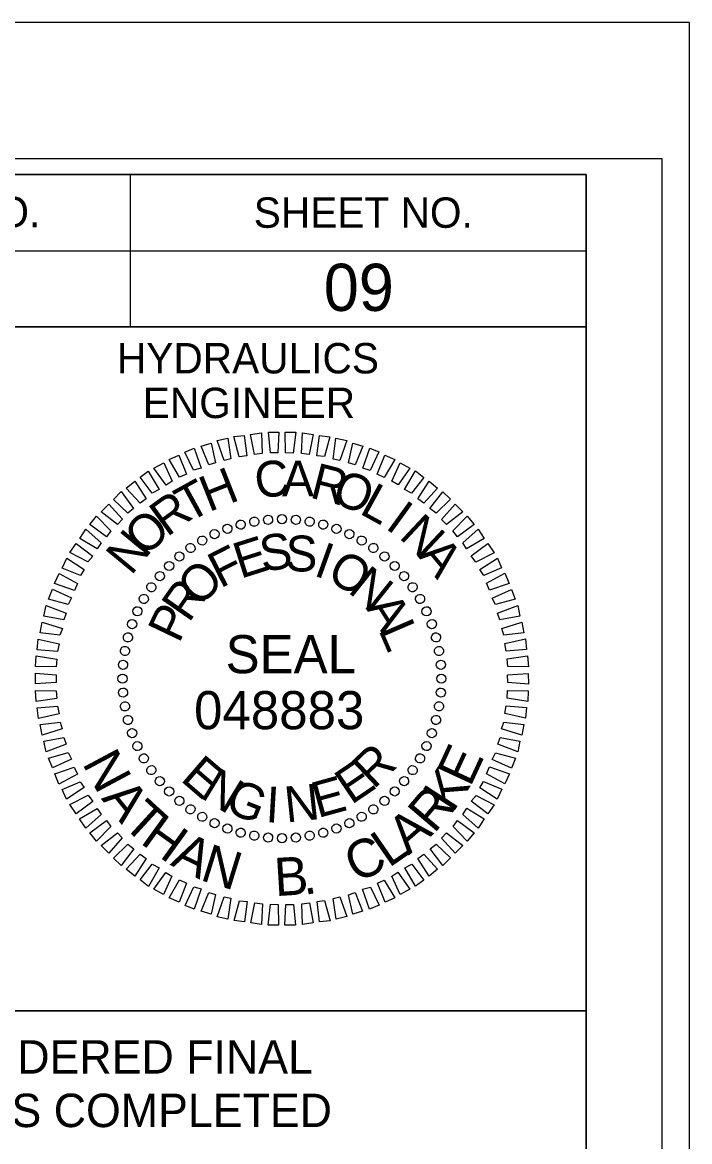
# Model space of a CAD drawing. Extents: x 1648862 to 1650739, y 844691 to 845791.
# Drawn here: x 1650436.5 to 1650546.3, y 845606.9 to 845791 of the extents above; entities that cross this region are included whole.
import ezdxf

# ---------------------------------------------------------------- set-up
doc = ezdxf.new("R2010")
doc.units = 0
for name, color, linetype in [('Default', 7, 'Continuous'), ('Prop Breaking of Exist Asph Pvmt', 7, 'Continuous'), ('Prop Conc Barrier Transition Section', 7, 'Continuous'), ('Prop Conc Drive Drop Type', 7, 'Continuous'), ('Prop DGN Element Guardrail', 7, 'Continuous'), ('Prop Easement Construction', 7, 'Continuous'), ('Prop Fence Woven Wire', 7, 'Continuous')]:
    doc.layers.add(name, color=color, linetype=linetype)

msp = doc.modelspace()

# ---------------------------------------------------------------- linework, layer by layer
at = {"layer": 'Prop Conc Barrier Transition Section'}
msp.add_lwpolyline([(1648862.28, 844691.02), (1650546.28, 844691.02), (1650546.28, 845791.02), (1648862.28, 845791.02)], close=True, dxfattribs=at)
at = {"layer": 'Prop Conc Drive Drop Type'}
for p, q in [((1650329.23, 845628.47), (1650529.27, 845628.47)), ((1650329.23, 845628.47), (1650529.27, 845628.47)), ((1650529.27, 845628.46), (1650529.27, 845604.96)), ((1650529.27, 845628.46), (1650529.27, 845604.96))]:
    msp.add_line(p, q, dxfattribs=at)
at = {"layer": 'Prop DGN Element Guardrail'}
for p, q in [((1650454.28, 845765.97), (1650454.28, 845740.97)), ((1650329.23, 845753.47), (1650529.28, 845753.47))]:
    msp.add_line(p, q, dxfattribs=at)
for points in [[(1650529.28, 845766.02), (1649029.28, 845766.02), (1649029.28, 844716.02), (1650529.28, 844716.02)], [(1650329.23, 845766.02), (1650529.28, 845766.02), (1650529.28, 845740.97), (1650329.23, 845740.97)], [(1650429.28, 845740.97), (1650529.28, 845740.97), (1650529.28, 845628.47), (1650429.28, 845628.47)]]:
    msp.add_lwpolyline(points, close=True, dxfattribs=at)
at = {"layer": 'Prop Easement Construction'}
msp.add_lwpolyline([(1648875.28, 844713.47), (1650541.78, 844713.47), (1650541.78, 845768.57), (1648875.28, 845768.57)], close=True, dxfattribs=at)
at = {"layer": 'Prop Fence Woven Wire'}
for p, q in [((1650472.41, 845708.44), (1650472.41, 845708.44)), ((1650474.7, 845708.89), (1650474.7, 845708.89)), ((1650476.94, 845709.25), (1650476.94, 845709.25)), ((1650479.24, 845709.34), (1650479.24, 845709.34)), ((1650481.55, 845709.22), (1650481.55, 845709.22)), ((1650483.8, 845708.9), (1650483.8, 845708.9)), ((1650486.01, 845708.46), (1650486.01, 845708.46)), ((1650468.15, 845706.9), (1650468.15, 845706.9)), ((1650470.22, 845707.77), (1650470.22, 845707.77)), ((1650488.21, 845707.77), (1650488.21, 845707.77)), ((1650490.32, 845706.87), (1650490.32, 845706.87)), ((1650464.16, 845704.58), (1650464.16, 845704.58)), ((1650466.13, 845705.82), (1650466.13, 845705.82)), ((1650492.38, 845705.86), (1650492.38, 845705.86)), ((1650494.28, 845704.58), (1650494.28, 845704.58)), ((1650462.35, 845703.24), (1650462.35, 845703.24)), ((1650496.14, 845703.2), (1650496.14, 845703.2)), ((1650460.66, 845701.64), (1650460.66, 845701.64)), ((1650497.79, 845701.66), (1650497.79, 845701.66)), ((1650459.12, 845699.99), (1650459.12, 845699.99)), ((1650499.38, 845699.96), (1650499.38, 845699.96)), ((1650457.74, 845698.14), (1650457.74, 845698.14)), ((1650500.72, 845698.16), (1650500.72, 845698.16)), ((1650456.46, 845696.23), (1650456.46, 845696.23)), ((1650501.96, 845696.19), (1650501.96, 845696.19)), ((1650455.45, 845694.18), (1650455.45, 845694.18)), ((1650503.04, 845694.17), (1650503.04, 845694.17)), ((1650454.55, 845692.07), (1650454.55, 845692.07)), ((1650503.91, 845692.09), (1650503.91, 845692.09)), ((1650453.85, 845689.86), (1650453.85, 845689.86)), ((1650504.58, 845689.91), (1650504.58, 845689.91)), ((1650453.42, 845687.66), (1650453.42, 845687.66)), ((1650505.04, 845687.62), (1650505.04, 845687.62)), ((1650453.1, 845685.4), (1650453.1, 845685.4)), ((1650505.39, 845685.37), (1650505.39, 845685.37)), ((1650452.98, 845683.1), (1650452.98, 845683.1)), ((1650479.23, 845683.09), (1650479.23, 845683.09)), ((1650505.48, 845683.07), (1650505.48, 845683.07)), ((1650453.07, 845680.8), (1650453.07, 845680.8)), ((1650505.37, 845680.77), (1650505.37, 845680.77)), ((1650453.42, 845678.56), (1650453.42, 845678.56)), ((1650505.04, 845678.52), (1650505.04, 845678.52)), ((1650453.88, 845676.26), (1650453.88, 845676.26)), ((1650504.61, 845676.31), (1650504.61, 845676.31)), ((1650454.55, 845674.08), (1650454.55, 845674.08)), ((1650503.92, 845674.1), (1650503.92, 845674.1)), ((1650455.42, 845672), (1650455.42, 845672)), ((1650503.01, 845672), (1650503.01, 845672)), ((1650456.5, 845669.98), (1650456.5, 845669.98)), ((1650502, 845669.94), (1650502, 845669.94)), ((1650457.74, 845668.02), (1650457.74, 845668.02)), ((1650500.73, 845668.03), (1650500.73, 845668.03)), ((1650459.08, 845666.21), (1650459.08, 845666.21)), ((1650499.35, 845666.18), (1650499.35, 845666.18)), ((1650460.68, 845664.51), (1650460.68, 845664.51)), ((1650497.81, 845664.53), (1650497.81, 845664.53)), ((1650462.32, 845662.97), (1650462.32, 845662.97)), ((1650496.11, 845662.93), (1650496.11, 845662.93)), ((1650464.18, 845661.59), (1650464.18, 845661.59)), ((1650466.08, 845660.32), (1650466.08, 845660.32)), ((1650492.34, 845660.36), (1650492.34, 845660.36)), ((1650494.3, 845661.59), (1650494.3, 845661.59)), ((1650468.14, 845659.31), (1650468.14, 845659.31)), ((1650490.32, 845659.28), (1650490.32, 845659.28)), ((1650470.25, 845658.4), (1650470.25, 845658.4)), ((1650472.46, 845657.71), (1650472.46, 845657.71)), ((1650474.66, 845657.28), (1650474.66, 845657.28)), ((1650476.92, 845656.95), (1650476.92, 845656.95)), ((1650479.22, 845656.83), (1650479.22, 845656.83)), ((1650481.52, 845656.93), (1650481.52, 845656.93)), ((1650483.76, 845657.28), (1650483.76, 845657.28)), ((1650486.05, 845657.74), (1650486.05, 845657.74)), ((1650488.24, 845658.4), (1650488.24, 845658.4))]:
    msp.add_line(p, q, dxfattribs=at)
for points in [[(1650472.21, 845719.57), (1650471.32, 845722.9), (1650473.04, 845723.09), (1650473.47, 845719.75)], [(1650474.72, 845719.93), (1650474.08, 845723.26), (1650475.86, 845723.5), (1650475.97, 845720.11)], [(1650477.33, 845720.24), (1650477.01, 845723.63), (1650478.73, 845723.61), (1650478.58, 845720.21)], [(1650479.84, 845720.23), (1650479.78, 845723.63), (1650481.5, 845723.6), (1650481.09, 845720.2)], [(1650482.45, 845720.12), (1650482.6, 845723.52), (1650484.34, 845723.23), (1650483.71, 845719.93)], [(1650484.97, 845719.74), (1650485.38, 845723.1), (1650487.11, 845722.86), (1650486.23, 845719.61)], [(1650467.22, 845718.23), (1650465.96, 845721.34), (1650467.57, 845721.84), (1650468.31, 845718.61)], [(1650469.71, 845718.95), (1650468.56, 845722.23), (1650470.33, 845722.62), (1650470.81, 845719.23)], [(1650487.65, 845719.21), (1650488.11, 845722.62), (1650489.9, 845722.23), (1650488.75, 845718.97)], [(1650490.17, 845718.58), (1650490.9, 845721.83), (1650492.53, 845721.34), (1650491.27, 845718.23)], [(1650462.39, 845716.21), (1650460.66, 845719.11), (1650462.27, 845719.87), (1650463.53, 845716.7)], [(1650464.67, 845717.35), (1650463.26, 845720.36), (1650464.82, 845721.01), (1650465.97, 845717.68)], [(1650492.54, 845717.68), (1650493.68, 845720.99), (1650495.16, 845720.39), (1650493.75, 845717.33)], [(1650494.91, 845716.72), (1650496.16, 845719.83), (1650497.79, 845719.13), (1650496.07, 845716.17)], [(1650460.16, 845714.92), (1650458.18, 845717.71), (1650459.79, 845718.57), (1650461.15, 845715.56)], [(1650497.33, 845715.56), (1650498.69, 845718.57), (1650500.28, 845717.71), (1650498.34, 845714.95)], [(1650455.93, 845711.97), (1650453.63, 845714.44), (1650455.03, 845715.56), (1650456.91, 845712.66)], [(1650457.89, 845713.57), (1650455.9, 845716.2), (1650457.25, 845717.22), (1650459.02, 845714.22)], [(1650499.4, 845714.19), (1650501.17, 845717.25), (1650502.55, 845716.18), (1650500.56, 845713.58)], [(1650501.57, 845712.66), (1650503.45, 845715.57), (1650504.83, 845714.44), (1650502.57, 845711.94)], [(1650453.86, 845710.31), (1650451.52, 845712.57), (1650452.76, 845713.85), (1650454.84, 845711.06)], [(1650503.58, 845711.07), (1650505.68, 845713.83), (1650506.96, 845712.59), (1650504.59, 845710.3)], [(1650452.17, 845708.45), (1650449.47, 845710.55), (1650450.75, 845711.77), (1650452.99, 845709.3)], [(1650505.5, 845709.27), (1650507.7, 845711.77), (1650508.98, 845710.54), (1650506.3, 845708.45)], [(1650450.37, 845706.43), (1650447.62, 845708.42), (1650448.75, 845709.8), (1650451.09, 845707.38)], [(1650507.36, 845707.42), (1650509.72, 845709.82), (1650510.85, 845708.43), (1650508.11, 845706.39)], [(1650448.84, 845704.42), (1650445.99, 845706.14), (1650446.95, 845707.68), (1650449.5, 845705.42)], [(1650508.96, 845705.41), (1650511.49, 845707.65), (1650512.51, 845706.15), (1650509.61, 845704.43)], [(1650447.31, 845702.3), (1650444.35, 845703.81), (1650445.37, 845705.3), (1650448.13, 845703.25)], [(1650510.36, 845703.29), (1650513.1, 845705.33), (1650514.12, 845703.78), (1650511.11, 845702.26)], [(1650446.09, 845700.03), (1650443.09, 845701.28), (1650443.85, 845702.92), (1650446.7, 845701.03)], [(1650511.76, 845701.02), (1650514.66, 845702.9), (1650515.36, 845701.29), (1650512.41, 845700.03)], [(1650445.09, 845697.6), (1650441.83, 845698.75), (1650442.58, 845700.38), (1650445.59, 845698.76)], [(1650512.85, 845698.79), (1650515.9, 845700.41), (1650516.61, 845698.75), (1650513.39, 845697.65)], [(1650444.08, 845695.29), (1650440.83, 845696.17), (1650441.48, 845697.8), (1650444.64, 845696.39)], [(1650513.83, 845696.35), (1650516.99, 845697.76), (1650517.6, 845696.15), (1650514.37, 845695.26)], [(1650443.34, 845692.76), (1650440.09, 845693.39), (1650440.43, 845695.12), (1650443.74, 845693.87)], [(1650514.71, 845693.85), (1650518.03, 845695.11), (1650518.38, 845693.39), (1650515.09, 845692.76)], [(1650442.71, 845690.24), (1650439.46, 845690.6), (1650439.79, 845692.39), (1650443.11, 845691.35)], [(1650515.38, 845691.35), (1650518.66, 845692.4), (1650519, 845690.63), (1650515.71, 845690.26)], [(1650442.34, 845687.57), (1650438.99, 845687.82), (1650439.16, 845689.6), (1650442.58, 845688.83)], [(1650515.89, 845688.85), (1650519.28, 845689.64), (1650519.47, 845687.87), (1650516.13, 845687.6)], [(1650442.12, 845685.05), (1650438.72, 845685.1), (1650438.79, 845686.83), (1650442.2, 845686.31)], [(1650516.25, 845686.35), (1650519.64, 845686.82), (1650519.78, 845685.05), (1650516.38, 845685.09)], [(1650442.11, 845682.44), (1650438.72, 845682.22), (1650438.69, 845684), (1650442.09, 845683.69)], [(1650516.35, 845683.73), (1650519.75, 845683.95), (1650519.78, 845682.17), (1650516.37, 845682.48)], [(1650442.21, 845679.83), (1650438.82, 845679.35), (1650438.68, 845681.12), (1650442.08, 845681.08)], [(1650516.34, 845681.12), (1650519.74, 845681.07), (1650519.67, 845679.35), (1650516.26, 845679.86)], [(1650442.57, 845677.32), (1650439.18, 845676.53), (1650438.99, 845678.3), (1650442.34, 845678.57)], [(1650516.13, 845678.61), (1650519.48, 845678.35), (1650519.3, 845676.57), (1650515.89, 845677.35)], [(1650443.08, 845674.82), (1650439.81, 845673.77), (1650439.46, 845675.54), (1650442.75, 845675.91)], [(1650515.75, 845675.93), (1650519, 845675.57), (1650518.67, 845673.79), (1650515.36, 845674.83)], [(1650443.75, 845672.32), (1650440.43, 845671.06), (1650440.08, 845672.78), (1650443.37, 845673.41)], [(1650515.12, 845673.41), (1650518.37, 845672.79), (1650518.04, 845671.06), (1650514.72, 845672.31)], [(1650444.63, 845669.83), (1650441.47, 845668.41), (1650440.86, 845670.02), (1650444.09, 845670.92)], [(1650514.38, 845670.89), (1650517.64, 845670), (1650516.98, 845668.37), (1650513.82, 845669.78)], [(1650445.62, 845667.39), (1650442.56, 845665.76), (1650441.85, 845667.42), (1650445.07, 845668.53)], [(1650513.37, 845668.57), (1650516.64, 845667.42), (1650515.88, 845665.79), (1650512.87, 845667.41)], [(1650446.7, 845665.16), (1650443.81, 845663.28), (1650443.1, 845664.88), (1650446.06, 845666.14)], [(1650512.37, 845666.15), (1650515.37, 845664.89), (1650514.62, 845663.26), (1650511.76, 845665.14)], [(1650448.1, 845662.88), (1650445.37, 845660.84), (1650444.34, 845662.4), (1650447.35, 845663.91)], [(1650511.15, 845663.88), (1650514.11, 845662.36), (1650513.09, 845660.88), (1650510.33, 845662.92)], [(1650449.5, 845660.76), (1650446.97, 845658.52), (1650445.96, 845660.02), (1650448.85, 845661.74)], [(1650509.62, 845661.76), (1650512.48, 845660.03), (1650511.51, 845658.5), (1650508.96, 845660.75)], [(1650451.1, 845658.75), (1650448.74, 845656.35), (1650447.62, 845657.75), (1650450.35, 845659.78)], [(1650508.09, 845659.74), (1650510.84, 845657.75), (1650509.72, 845656.37), (1650507.37, 845658.79)], [(1650452.97, 845656.9), (1650450.76, 845654.4), (1650449.48, 845655.63), (1650452.17, 845657.72)], [(1650506.29, 845657.72), (1650509, 845655.63), (1650507.71, 845654.4), (1650505.47, 845656.87)], [(1650454.88, 845655.1), (1650452.78, 845652.35), (1650451.51, 845653.58), (1650453.87, 845655.87)], [(1650504.6, 845655.86), (1650506.94, 845653.6), (1650505.71, 845652.33), (1650503.62, 845655.12)], [(1650456.89, 845653.52), (1650455.01, 845650.61), (1650453.63, 845651.73), (1650455.89, 845654.23)], [(1650502.54, 845654.21), (1650504.83, 845651.74), (1650503.44, 845650.61), (1650501.56, 845653.51)], [(1650459.06, 845651.98), (1650457.29, 845648.92), (1650455.91, 845649.99), (1650457.9, 845652.59)], [(1650461.13, 845650.61), (1650459.77, 845647.6), (1650458.18, 845648.46), (1650460.12, 845651.22)], [(1650498.3, 845651.26), (1650500.28, 845648.47), (1650498.68, 845647.6), (1650497.32, 845650.61)], [(1650500.58, 845652.6), (1650502.56, 845649.97), (1650501.22, 845648.95), (1650499.44, 845651.96)], [(1650463.55, 845649.45), (1650462.3, 845646.34), (1650460.67, 845647.04), (1650462.39, 845650)], [(1650496.07, 845649.96), (1650497.8, 845647.06), (1650496.19, 845646.3), (1650494.93, 845649.47)], [(1650465.92, 845648.5), (1650464.78, 845645.18), (1650463.3, 845645.78), (1650464.72, 845648.84)], [(1650468.29, 845647.6), (1650467.57, 845644.34), (1650465.94, 845644.83), (1650467.19, 845647.94)], [(1650491.25, 845647.94), (1650492.5, 845644.83), (1650490.89, 845644.33), (1650490.15, 845647.56)], [(1650493.79, 845648.82), (1650495.2, 845645.82), (1650493.65, 845645.16), (1650492.49, 845648.49)], [(1650470.81, 845646.96), (1650470.35, 845643.55), (1650468.57, 845643.94), (1650469.71, 845647.2)], [(1650473.49, 845646.43), (1650473.08, 845643.08), (1650471.35, 845643.31), (1650472.23, 845646.57)], [(1650476.01, 845646.06), (1650475.86, 845642.65), (1650474.13, 845642.94), (1650474.75, 845646.24)], [(1650478.62, 845645.95), (1650478.68, 845642.55), (1650476.96, 845642.57), (1650477.37, 845645.98)], [(1650481.13, 845645.94), (1650481.46, 845642.54), (1650479.73, 845642.57), (1650479.88, 845645.97)], [(1650483.74, 845646.24), (1650484.38, 845642.91), (1650482.6, 845642.67), (1650482.49, 845646.07)], [(1650486.25, 845646.6), (1650487.14, 845643.27), (1650485.42, 845643.08), (1650485, 845646.42)], [(1650488.75, 845647.22), (1650489.9, 845643.95), (1650488.13, 845643.55), (1650487.65, 845646.94)]]:
    msp.add_lwpolyline(points, close=True, dxfattribs=at)
for centre, major_axis in [((1650476.95, 845709.21), (-0.066, 0.75)), ((1650479.23, 845709.31), (0, 0.753)), ((1650481.52, 845709.21), (0.066, 0.75)), ((1650470.26, 845707.73), (-0.258, 0.708)), ((1650472.44, 845708.42), (-0.195, 0.727)), ((1650474.68, 845708.92), (-0.131, 0.742)), ((1650483.79, 845708.92), (0.131, 0.742)), ((1650486.02, 845708.42), (0.195, 0.727)), ((1650488.2, 845707.73), (0.258, 0.708)), ((1650466.12, 845705.8), (-0.376, 0.652)), ((1650468.15, 845706.86), (-0.318, 0.682)), ((1650490.32, 845706.86), (0.318, 0.682)), ((1650492.35, 845705.8), (0.376, 0.652)), ((1650464.19, 845704.57), (-0.432, 0.617)), ((1650494.27, 845704.57), (0.432, 0.617)), ((1650462.37, 845703.18), (-0.484, 0.577)), ((1650496.09, 845703.18), (0.484, 0.577)), ((1650459.14, 845699.95), (-0.577, 0.484)), ((1650460.69, 845701.63), (-0.532, 0.532)), ((1650497.78, 845701.63), (0.532, 0.532)), ((1650499.32, 845699.95), (0.577, 0.484)), ((1650457.75, 845698.13), (-0.617, 0.432)), ((1650500.72, 845698.13), (0.617, 0.432)), ((1650456.52, 845696.2), (-0.652, 0.376)), ((1650501.95, 845696.2), (0.652, 0.376)), ((1650455.46, 845694.17), (-0.682, 0.318)), ((1650503, 845694.17), (0.682, 0.318)), ((1650454.59, 845692.06), (-0.708, 0.258)), ((1650503.88, 845692.06), (0.708, 0.258)), ((1650453.9, 845689.87), (-0.727, 0.195)), ((1650504.57, 845689.87), (0.727, 0.195)), ((1650453.4, 845687.64), (-0.742, 0.131)), ((1650505.06, 845687.64), (0.742, 0.131)), ((1650453.1, 845685.37), (-0.75, 0.066)), ((1650505.36, 845685.37), (0.75, 0.066)), ((1650453, 845683.09), (-0.753, 0)), ((1650505.46, 845683.09), (0.753, 0)), ((1650453.1, 845680.8), (-0.75, -0.066)), ((1650505.36, 845680.8), (0.75, -0.066)), ((1650453.4, 845678.53), (-0.742, -0.131)), ((1650505.06, 845678.53), (0.742, -0.131)), ((1650453.9, 845676.3), (-0.727, -0.195)), ((1650504.57, 845676.3), (0.727, -0.195)), ((1650454.59, 845674.12), (-0.708, -0.258)), ((1650503.88, 845674.12), (0.708, -0.258)), ((1650455.46, 845672), (-0.682, -0.318)), ((1650503, 845672), (0.682, -0.318)), ((1650456.52, 845669.97), (-0.652, -0.376)), ((1650501.95, 845669.97), (0.652, -0.376)), ((1650457.75, 845668.04), (-0.617, -0.432)), ((1650500.72, 845668.04), (0.617, -0.432)), ((1650459.14, 845666.23), (-0.577, -0.484)), ((1650499.32, 845666.23), (0.577, -0.484)), ((1650460.69, 845664.54), (-0.532, -0.532)), ((1650497.78, 845664.54), (0.532, -0.532)), ((1650462.37, 845662.99), (-0.484, -0.577)), ((1650464.19, 845661.6), (-0.432, -0.617)), ((1650494.27, 845661.6), (0.432, -0.617)), ((1650496.09, 845662.99), (0.484, -0.577)), ((1650466.12, 845660.37), (-0.376, -0.652)), ((1650492.35, 845660.37), (0.376, -0.652)), ((1650468.15, 845659.32), (-0.318, -0.682)), ((1650470.26, 845658.44), (-0.258, -0.708)), ((1650472.44, 845657.75), (-0.195, -0.727)), ((1650486.02, 845657.75), (0.195, -0.727)), ((1650488.2, 845658.44), (0.258, -0.708)), ((1650490.32, 845659.32), (0.318, -0.682)), ((1650474.68, 845657.26), (-0.131, -0.742)), ((1650476.95, 845656.96), (-0.066, -0.75)), ((1650479.23, 845656.86), (0, -0.753)), ((1650481.52, 845656.96), (0.066, -0.75)), ((1650483.79, 845657.26), (0.131, -0.742))]:
    msp.add_ellipse(centre, major_axis=major_axis, ratio=0.999708, dxfattribs=at)

# ---------------------------------------------------------------- texts
at = {"layer": 'Default'}
for s, rotation, p in [('N', 298.0773, (1650446.31, 845669.19)), ('E', 65.2198, (1650510.2, 845665.13)), ('K', 57.024, (1650507.33, 845660.9)), ('A', 308.6891, (1650449.42, 845663.36)), ('R', 49.6233, (1650504.25, 845657.47)), ('T', 317.4354, (1650452.76, 845659.05)), ('H', 324.1633, (1650455.75, 845656.11)), ('A', 40.877, (1650500.07, 845653.97)), ('A', 334.0411, (1650460.72, 845652.48)), ('C', 25.1886, (1650491.43, 845649.42)), ('L', 34.6689, (1650496.8, 845651.89)), ('N', 342.7874, (1650465.58, 845650.01)), ('B', 3.4911, (1650478.14, 845647.31)), ('.', 11.1059, (1650482.89, 845647.47))]:
    msp.add_text(s, height=6.27, rotation=rotation, dxfattribs=at).set_placement(p)
at = {"layer": 'Prop Breaking of Exist Asph Pvmt'}
msp.add_text('09', height=7.75, dxfattribs=at).set_placement((1650486.11, 845743.57))
at = {"layer": 'Prop Conc Drive Drop Type'}
for s, p in [('DOCUMENT NOT CONSIDERED FINAL', (1650350.3, 845618.13)), ('DOCUMENT NOT CONSIDERED FINAL', (1650350.3, 845618.13)), ('UNLESS ALL SIGNATURES COMPLETED', (1650345.23, 845609.33)), ('UNLESS ALL SIGNATURES COMPLETED', (1650345.23, 845609.33))]:
    msp.add_text(s, height=5.5, dxfattribs=at).set_placement(p)
at = {"layer": 'Prop DGN Element Guardrail'}
for s, height, p in [('PROJECT REFERENCE NO.', 5.0001, (1650351.44, 845757.34)), ('SHEET NO.', 5, (1650474.59, 845757.24)), ('HYDRAULICS', 5, (1650452.09, 845733.29)), ('ENGINEER', 5, (1650456.34, 845725.94))]:
    msp.add_text(s, height=height, dxfattribs=at).set_placement(p)
at = {"layer": 'Prop Fence Woven Wire'}
for s, rotation, p in [('H', 21.6195, (1650467.2, 845710.44)), ('C', 7.2199, (1650475.11, 845712.67)), ('A', 0.0203, (1650479.23, 845713.05)), ('R', 345.6211, (1650483.63, 845712.92)), ('T', 28.8198, (1650463.83, 845708.65)), ('O', 338.4212, (1650487.14, 845712.2)), ('L', 331.2209, (1650491.78, 845710.34)), ('R', 36.0205, (1650460.31, 845706.29)), ('I', 324.0201, (1650496.06, 845707.91)), ('O', 43.2217, (1650456.76, 845702.99)), ('N', 316.8189, (1650498.33, 845706.33)), ('N', 50.4235, (1650454.41, 845699.91)), ('E', 17.6111, (1650472.41, 845699.49)), ('S', 8.2556, (1650476, 845700.65)), ('S', 358.9004, (1650479.76, 845700.77)), ('F', 26.967, (1650469.09, 845697.87)), ('I', 340.1896, (1650484.27, 845700.12)), ('A', 309.6172, (1650501.47, 845703.29)), ('O', 330.8335, (1650486.37, 845699.42)), ('O', 45.6812, (1650465.69, 845694.72)), ('N', 321.4766, (1650489.91, 845697.39)), ('R', 55.0397, (1650463.91, 845692.13)), ('P', 64.3989, (1650462.29, 845688.75)), ('A', 302.7603, (1650492.94, 845694.73)), ('L', 293.4009, (1650495.04, 845691.15)), ('R', 43.4814, (1650494.3, 845664.78)), ('E', 319.2769, (1650462.37, 845666.42)), ('E', 34.1241, (1650490.63, 845662.26)), ('N', 328.634, (1650465.56, 845663.65)), ('G', 337.9902, (1650469.57, 845661.37)), ('E', 15.4118, (1650485.12, 845660.13)), ('I', 356.7012, (1650476.45, 845659.5)), ('N', 6.0564, (1650479.96, 845659.41))]:
    msp.add_text(s, height=5.9, rotation=rotation, dxfattribs=at).set_placement(p)
for s, height, p in [('SEAL', 6.273, (1650469.96, 845683.97)), ('048883', 6.275, (1650464.78, 845674.77))]:
    msp.add_text(s, height=height, dxfattribs=at).set_placement(p)

doc.saveas('drawing.dxf')
